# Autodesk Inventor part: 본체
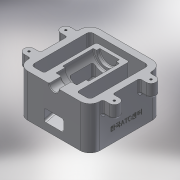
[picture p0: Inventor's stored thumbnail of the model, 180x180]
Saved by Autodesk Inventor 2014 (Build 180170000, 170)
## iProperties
Created: 2018-01
Part Number: 본체
Material: Aluminum 6061
Document SubType Name: Modeling
Designer: user
Density: 2.71 g/cm^3
Appearance: Aluminum - Flat
Mass: 998.969 g
Surface Area: 834.538 cm^2
Volume: 368.623 cm^3
Author: user
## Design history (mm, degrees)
sketch "Sketch1"
  geometry: L1 (-40, 55)-(40, 55); L2 (55, 40)-(55, -40); L3 (40, -55)-(-40, -55); L4 (-55, -40)-(-55, 40); L5 (-55, 55)-(55, -55); L6 (55, 55)-(-55, -55); L7 (40, 45)-(-40, 45); L8 (-45, 40)-(-45, -40); L9 (-40, -45)-(40, -45); L10 (45, -40)-(45, 40); A1 r 15 centre (-40, 40) between (-40, 55) and (-55, 40); A2 r 15 centre (40, 40) between (55, 40) and (40, 55); A3 r 15 centre (40, -40) between (40, -55) and (55, -40); A4 r 15 centre (-40, -40) between (-55, -40) and (-40, -55); A5 r 5 centre (-40, 40) between (-40, 45) and (-45, 40); A6 r 5 centre (-40, -40) between (-45, -40) and (-40, -45); A7 r 5 centre (40, -40) between (40, -45) and (45, -40); A8 r 5 centre (40, 40) between (45, 40) and (40, 45); 1 further point
  constraints: 20 end point, 16 point on circle, 8 centre point, 8 point on line, 8 tangent, 4 parallel, 3 equal radius, 2 midpoint, 2 perpendicular, 1 horizontal, 7 other
  dimensions: "d0" = 110 distance of L5.end L6.end; "d1" = 110 distance of L6.start L5.end; "d2" = 15 radius of A1; "d3" = 10 distance between parallel lines of L1 L7
extrude "Extrusion1" new body sketch "Sketch1" distance "d4" = 65; taper "d5" = 0 deg
sketch "Sketch3"
  geometry: L1 (-40, -55)-(40, -55) reference; L2 (-55, 40)-(-55, -40) reference; L3 (-65, -35.5)-(-55, -35.5); L4 (-65, -20.5)-(-55, -20.5); A1 r 7.5 centre (-65, -28) between (-65, -20.5) and (-65, -35.5); 1 further point
  constraints: 4 end point, 2 point on circle, 2 point on line, 2 tangent, 1 centre point, 1 parallel, 1 perpendicular
  dimensions: "d6" = 15 diameter of A1; "d7" = 27 distance from line of L1 A1.centre; "d8" = 10 distance from line of L2 A1.centre
extrude "Extrusion2" join sketch "Sketch3" distance "d9" = 20; taper "d10" = 0 deg
pattern_linear "Rectangular Pattern1" dims "d13" = 56
mirror "Mirror1"
hole "Hole1" diameter "d16" = 3.242; stored, may be unused: countersink angle "d20" = 90 deg, drill point angle "d22" = 118 deg; dims "d14" = 10, "d15" = 10, "d17" = 9, "d18" = 4, "d19" = 2, "d21" = 11
pattern_linear "Rectangular Pattern2" dims "d25" = 56
sketch "Sketch4"
  geometry: L1 (40, -45)-(-40, -45) reference; L2 (-25, -45)-(25, -45); L3 (25, -45)-(25, 35); L4 (25, 35)-(-25, 35); L5 (-25, 35)-(-25, -45); L6 (0, 0)-(0, -45); L7 (40, 55)-(-40, 55) reference
  constraints: 10 end point, 2 parallel, 1 horizontal, 1 midpoint, 1 perpendicular, 1 point on line, 1 vertical
  dimensions: "d29" = 50 distance of L3.end L4.end; "d30" = 20 distance between parallel lines of L7 L4
extrude "Extrusion3" join sketch "Sketch4" distance "d31" = 65; taper "d32" = 0 deg
sketch "Sketch5"
  geometry: L1 (-40, -55)-(40, -55) reference; L2 (0, -55)-(0, 30); L3 (0, 30)-(-14, 30); L4 (-15, 29)-(-15, 25); L5 (-15, 25)-(-19, 25); L6 (-20, 24)-(-20, -21); L7 (-19, -22)-(-16, -22); L8 (-16, -22)-(-16, -35); L9 (-15, -36)-(-7.5, -36); L10 (-7.5, -36)-(-7.5, -55); L11 (0, -55)-(-7.5, -55); A1 r 1 centre (-14, 29) between (-14, 30) and (-15, 29); A2 r 1 centre (-19, 24) between (-19, 25) and (-20, 24); A3 r 1 centre (-19, -21) between (-20, -21) and (-19, -22); A4 r 1 centre (-15, -35) between (-16, -35) and (-15, -36); 1 further point
  constraints: 20 end point, 8 point on circle, 8 tangent, 6 parallel, 4 centre point, 4 perpendicular, 3 equal radius, 1 midpoint, 1 point on line
  dimensions: "d33" = 30 diameter of L4 L2; "d34" = 40 diameter of L6 L2; "d35" = 32 diameter of L8 L2; "d36" = 15 diameter of L10 L2; "d37" = 19 distance between parallel lines of L1 L9; "d38" = 14 distance between parallel lines of L7 L9; "d39" = 47 distance between parallel lines of L5 L7; "d40" = 5 distance between parallel lines of L3 L5; "d41" = 1 radius of A1
revolve "Revolution1" sketch "Sketch5" stored, may be unused: angle "d42" = 90 deg
chamfer "Chamfer1" distance "d43" = 1; stored, may be unused: second distance "d44" = 2, angle "d45" = 45 deg
sketch "Sketch6"
  geometry: L1 (0, 55)-(65, 55) reference; L2 (0, 45)-(0, -35) reference; L3 (0, 40)-(0, 55) reference; L4 (65, -35)-(0, -35) reference; L5 (6.262, 45)-(0, 45); L6 (9.16, 42.776)-(30, -35); A1 r 3 centre (6.262, 42) between (9.16, 42.776) and (6.262, 45); 1 further point
  constraints: 4 end point, 2 point on circle, 2 point on line, 2 tangent, 1 centre point, 1 perpendicular
  dimensions: "d46" = 30 distance from line of L2 L6.end; "d47" = 10 distance between parallel lines of L1 L5; "d49" = 105 deg angle of L5 L6; "d50" = 3 radius of A1
extrude "Extrusion4" cut sketch "Sketch6" stored distance "d51" = 65; taper "d52" = 0 deg
sketch "Sketch7"
  geometry: L1 (30, -35)-(9.16, 42.776) reference; L2 (0, 55)-(65, 55) reference; L3 (30.561, -17.776)-(11.061, 55); L4 (45, -24)-(45, 21) reference; L5 (45, -20)-(33.459, -20); L6 (65, -25)-(46, -25) reference; L7 (29.061, 55)-(38.647, 19.224); L8 (41.545, 17)-(45, 17); L9 (65, 22)-(46, 22) reference; L10 (45, 17)-(55, 17); L11 (55, 17)-(55, -20); L12 (55, -20)-(45, -20); A1 r 3 centre (41.545, 20) between (38.647, 19.224) and (41.545, 17); A2 r 3 centre (33.459, -17) between (30.561, -17.776) and (33.459, -20); 1 further point
  constraints: 14 end point, 4 parallel, 4 point on circle, 4 point on line, 4 tangent, 3 perpendicular, 2 centre point, 1 equal radius
  dimensions: "d53" = 5 distance between parallel lines of L1 L3; "d54" = 5 distance between parallel lines of L6 L5; "d55" = 18 distance of L3.end L7.start; "d56" = 5 distance between parallel lines of L9 L8; "d57" = 3 radius of A1; "d60" = 10 distance between parallel lines of L4 L11
extrude "Extrusion6" cut sketch "Sketch7" stored distance "d61" = 30; taper "d62" = 0 deg
sketch "Sketch8"
  geometry: L1 (0, 0)-(80, 0) reference; L2 (-15, 0)-(-15, 65) reference; 2 further points
  constraints: 1 other
  dimensions: "d63" = 20 distance from line of L1 point (40, 20); "d64" = 55 distance from line of L2 point (40, 20)
emboss "Emboss1" sketch "Sketch8" dims "d65" = 0.5, "d66" = 0
fillet "Fillet1" dims "d67" = 3
fillet "Fillet2" dims "d68" = 3
fillet "Fillet3" dims "d69" = 3
fillet "Fillet4" dims "d70" = 3
chamfer "Chamfer2" distance "d71" = 1; stored, may be unused: second distance "d72" = 2, angle "d73" = 45 deg
body "Solid1"
